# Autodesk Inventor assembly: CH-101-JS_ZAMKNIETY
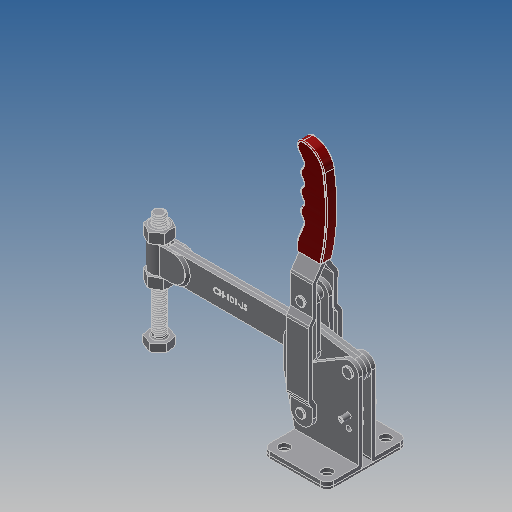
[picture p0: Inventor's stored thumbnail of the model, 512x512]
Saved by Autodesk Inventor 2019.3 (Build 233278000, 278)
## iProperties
Company: Î¢ÈíÖÐ¹ú
Created: 2012-09
Part Number: CH-101-JS_ZAMKNIETY
Material: Ogólny
Description: STEP AP203
Document SubType Name: Assembly
Designer: CADENGINEERING4
Sending System: SolidWorks 2010
Preprocessor: SwSTEP 2.0
Title: CH-101-JS.STEP
Author: Î¢ÈíÓÃ»§
Revision Number: ÈÎºÎ
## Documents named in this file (15)
- E:\STRONA\Piotrek\CH-101-JS\CH-101-JS_ZAMKNIETY.iam
- E:\STRONA\Piotrek\CH-101-JS\CH-10247-08.ipt
- E:\STRONA\Piotrek\CH-101-JS\CH-101-J-06.ipt
- E:\STRONA\Piotrek\CH-101-JS\CH-101-J-01 FLANGED BASE.ipt
- E:\STRONA\Piotrek\CH-101-JS\CH-SA-58500 NUT.ipt
- E:\STRONA\Piotrek\CH-101-JS\CH-101-J-11.ipt
- E:\STRONA\Piotrek\CH-101-JS\CH-SA-58500 SPINDLE SUPPLIED.ipt
- E:\STRONA\Piotrek\CH-101-JS\3-8-16 LOCK NUT.ipt
- E:\STRONA\Piotrek\CH-101-JS\CH-101-JS-02 SOLID BAR_Ä¬ÈÏ_°´¼Ó¹¤_.ipt
- E:\STRONA\Piotrek\CH-101-JS\CH-101-J-05.ipt
- E:\STRONA\Piotrek\CH-101-JS\CH-10247-09.ipt
- E:\STRONA\Piotrek\CH-101-JS\CH-101-J-04 CONNECTING-PLATE.ipt
- E:\STRONA\Piotrek\CH-101-JS\CH-10247-05.ipt
- E:\STRONA\Piotrek\CH-101-JS\CH-101-J-07.ipt
- E:\STRONA\Piotrek\CH-101-JS\CH-101-J-03 HANDLE.ipt
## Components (19 placed, 19 different names)
1. CH-10247-08_1
2. CH-101-J-06_2
3. CH-101-J-01 FLANGED BASE_3
4. CH-SA-58500 NUT_4
5. CH-101-J-11_5
6. CH-SA-58500 SPINDLE SUPPLIED_6
7. CH-101-J-11_7
8. 3-8-16 LOCK NUT_8
9. CH-SA-58500 NUT_9
10. CH-101-JS-02 SOLID BAR_Ä¬ÈÏ<°´¼Ó¹¤>_10
11. CH-101-J-05_11
12. 3-8-16 LOCK NUT_12
13. CH-10247-09_13
14. CH-101-J-04 CONNECTING-PLATE_14
15. CH-10247-05_15
16. CH-101-J-06_16
17. CH-101-J-07_17
18. CH-101-J-03 HANDLE_18
19. CH-10247-08_19
